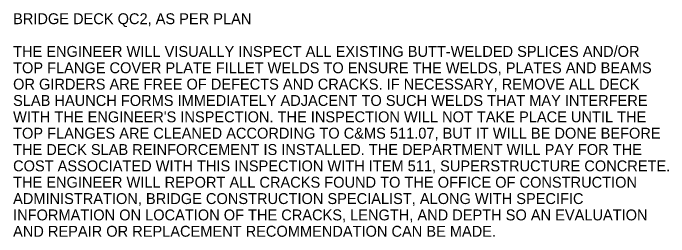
# Model space of a CAD drawing. Extents: x -11.1 to 53.9, y -2 to 22.
# Drawn here: x -10.45 to -2.03, y 13.19 to 16.06 of the extents above; entities that cross this region are included whole.
import ezdxf

# ---------------------------------------------------------------- set-up
doc = ezdxf.new("R2010")
doc.units = 0
doc.layers.add('BR_P_Gen_Text', color=7, linetype='Continuous')

msp = doc.modelspace()

# ---------------------------------------------------------------- texts
at = {"layer": 'BR_P_Gen_Text'}
for s, p in [('BRIDGE DECK QC2, AS PER PLAN', (-10.4513, 15.9195)), ('THE ENGINEER WILL VISUALLY INSPECT ALL EXISTING BUTT-WELDED SPLICES AND/OR', (-10.4513, 15.4995)), ('TOP FLANGE COVER PLATE FILLET WELDS TO ENSURE THE WELDS, PLATES AND BEAMS', (-10.4513, 15.2895)), ('OR GIRDERS ARE FREE OF DEFECTS AND CRACKS. IF NECESSARY, REMOVE ALL DECK ', (-10.4513, 15.0795)), ('SLAB HAUNCH FORMS IMMEDIATELY ADJACENT TO SUCH WELDS THAT MAY INTERFERE', (-10.4513, 14.8695)), ("WITH THE ENGINEER'S INSPECTION. THE INSPECTION WILL NOT TAKE PLACE UNTIL THE", (-10.4513, 14.6595)), ('TOP FLANGES ARE CLEANED ACCORDING TO C&MS 511.07, BUT IT WILL BE DONE BEFORE', (-10.4513, 14.4495)), ('THE DECK SLAB REINFORCEMENT IS INSTALLED. THE DEPARTMENT WILL PAY FOR THE', (-10.4513, 14.2395)), ('COST ASSOCIATED WITH THIS INSPECTION WITH ITEM 511, SUPERSTRUCTURE CONCRETE. ', (-10.4513, 14.0295)), ('THE ENGINEER WILL REPORT ALL CRACKS FOUND TO THE OFFICE OF CONSTRUCTION', (-10.4513, 13.8195)), ('ADMINISTRATION, BRIDGE CONSTRUCTION SPECIALIST, ALONG WITH SPECIFIC ', (-10.4513, 13.6095)), ('INFORMATION ON LOCATION OF THE CRACKS, LENGTH, AND DEPTH SO AN EVALUATION ', (-10.4513, 13.3995)), ('AND REPAIR OR REPLACEMENT RECOMMENDATION CAN BE MADE.', (-10.4513, 13.1895))]:
    msp.add_text(s, height=0.14, dxfattribs=at).set_placement(p)

doc.saveas('drawing.dxf')
